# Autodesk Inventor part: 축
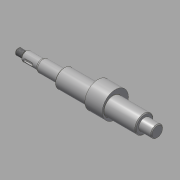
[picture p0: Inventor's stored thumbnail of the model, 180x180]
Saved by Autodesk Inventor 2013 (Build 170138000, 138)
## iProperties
Created: 2015-12
Part Number: 축
Document SubType Name: Modeling
Designer: mdu
Density: 7.86 g/cm^3
Material: 강철, 연강
Mass: 489.712 g
Surface Area: 127.382 cm^2
Volume: 62.3043 cm^3
Author: mdu
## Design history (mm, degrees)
sketch "스케치1"
  geometry: L1 (62, 100.9)-(62, 67.1) reference; L2 (51, 101.2)-(51, 84) reference; L3 (-51, 84)-(-51, 101.2) reference; L4 (-62, 67.1)-(-62, 100.9) reference; L5 (-51.6, 91.5)-(-61.4, 91.5) reference; L6 (51.6, 91.5)-(61.4, 91.5) reference; L7 (67, 84)-(-109, 84); L8 (-77, 64.201)-(-77, 103.799) reference; L9 (67, 84)-(67, 91.5); L10 (67, 91.5)-(51, 91.5); L11 (51, 91.5)-(51, 95.5); L12 (51, 95.5)-(-51, 95.5); L13 (-51, 95.5)-(-51, 91.5); L14 (-51, 91.5)-(-79, 91.5); L15 (-79, 91.5)-(-79, 90); L16 (-79, 90)-(-99, 90); L17 (-99, 90)-(-99, 87); L18 (-100.5, 88)-(-109, 88); L19 (-109, 88)-(-109, 84); L20 (-99, 87)-(-100.5, 87); L21 (-100.5, 87)-(-100.5, 88); 2 further points
  constraints: 32 end point, 7 parallel, 6 point on line, 5 perpendicular, 2 collinear, 2 horizontal, 1 midpoint, 4 other
  dimensions: "d0" = 5 distance from line of L7.start L1; "d2" = 2 distance between parallel lines of L15 L8; "d3" = 23 diameter of L12 L7; "d4" = 12 diameter of L16 L7; "d5" = 1.5 distance of L17.end L20.end; "d6" = 6 diameter of L20 L7; "d7" = 20 distance of L15.end L16.end; "d8" = 10 distance between parallel lines of L17 L19; "d9" = 8 diameter of L18 L7
revolve "회전1" sketch "스케치1" stored, may be unused: angle "d10" = 90 deg
sketch "스케치2"
  geometry: C1 r 11.5 at (84, 0) reference; C2 r 11.5 at (84, 0) reference; C3 r 16.5 at (87, 0); 1 further point
  constraints: 1 centre point, 1 horizontal alignment
  dimensions: "d11" = 33 diameter of C3; "d12" = 3 distance of C3.centre C1.centre
extrude "돌출1" join sketch "스케치2" stored distance "d13" = 22; taper "d14" = 0 deg
chamfer "모따기1" distance "d15" = 1; stored, may be unused: second distance "d16" = 2, angle "d17" = 45 deg
feature "스레드1" dims "d18" = 10, "d19" = 0
node "작업 평면1"
sketch "스케치3"
  geometry: L1 (-5, -2)-(3, -2); L2 (3, 2)-(-5, 2); L3 (-10, -5)-(-10, 5) reference; A1 r 2 centre (3, 0) between (3, -2) and (3, 2); A2 r 2 centre (-5, 0) between (-5, 2) and (-5, -2); 2 further points
  constraints: 4 end point, 4 point on circle, 4 tangent, 2 centre point, 1 horizontal, 1 horizontal alignment, 1 midpoint, 1 parallel
  dimensions: "d20" = 4 distance between parallel lines of L1 L2; "d21" = 12 dimension on A1 A2; "d22" = 3 distance edge to line of A2 L3
extrude "돌출2" cut sketch "스케치3" distance "d23" = 2.5; taper "d24" = 0 deg
fillet "모깎기1" dims "d25" = 0.3
fillet "모깎기2" dims "d26" = 3
node "솔리드1"
node "참조1"
node "참조2"
node "참조3"
node "참조4"
node "참조5"
node "투영된 루프1"
